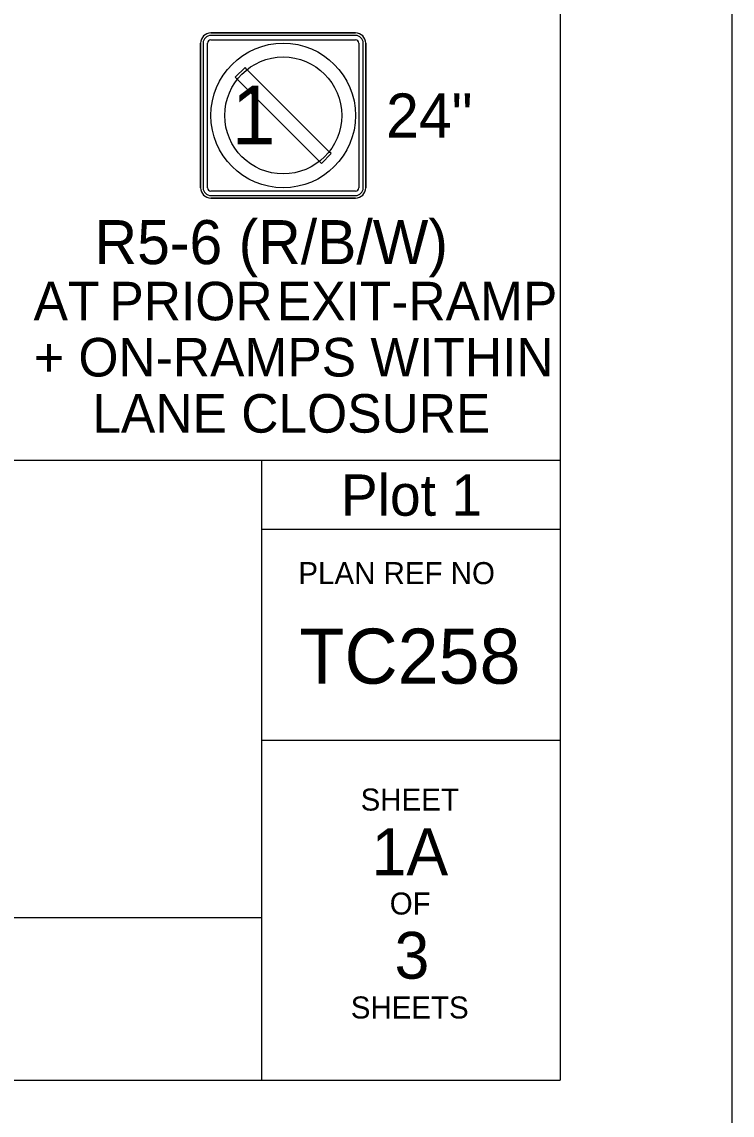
# Model space of a CAD drawing. Extents: x 99999 to 100116, y 99995 to 100013.
# Drawn here: x 100014.772 to 100016.062, y 99999.937 to 100001.922 of the extents above; entities that cross this region are included whole.
import ezdxf

# ---------------------------------------------------------------- set-up
doc = ezdxf.new("R2010")
doc.units = 0
for name, color, linetype in [('SH_GI_PlotLimits', 7, 'Continuous'), ('SH_GI_SheetBorder', 7, 'Continuous'), ('SH_GI_SheetLocationText', 7, 'Continuous'), ('SH_GI_SheetTextInCells', 7, 'Continuous'), ('SH_GI_TitleBlockText', 7, 'Continuous'), ('TR_SN_ConstructionSigns', 7, 'Continuous')]:
    doc.layers.add(name, color=color, linetype=linetype)

msp = doc.modelspace()

# ---------------------------------------------------------------- linework, layer by layer
at = {"layer": 'SH_GI_PlotLimits'}
msp.add_lwpolyline([(99999.0625, 99999.6875), (100016.0625, 99999.6875), (100016.0625, 100010.6875), (99999.0625, 100010.6875)], close=True, dxfattribs=at)
at = {"layer": 'SH_GI_SheetBorder'}
for p, q in [((100015.75, 100010.375), (100015.75, 100000)), ((100000, 100001.1259), (100015.75, 100001.1259)), ((100015.2079, 100001.1259), (100015.2079, 100000)), ((100015.2079, 100001.0008), (100015.75, 100001.0008)), ((100015.2079, 100000.6176), (100015.75, 100000.6176)), ((100012.2055, 100000.2955), (100015.2079, 100000.2955)), ((100000, 100000), (100015.75, 100000))]:
    msp.add_line(p, q, dxfattribs=at)
at = {"layer": 'TR_SN_ConstructionSigns'}
for p, q in [((100015.3783, 100001.9019), (100015.1158, 100001.9019)), ((100015.1158, 100001.9019), (100015.3783, 100001.9019)), ((100015.3783, 100001.9019), (100015.1158, 100001.9019)), ((100015.3783, 100001.8972), (100015.1158, 100001.8972)), ((100015.1158, 100001.8894), (100015.3783, 100001.8894)), ((100015.0971, 100001.8831), (100015.0971, 100001.6206)), ((100015.0971, 100001.6206), (100015.0971, 100001.8831)), ((100015.0971, 100001.8831), (100015.0971, 100001.6206)), ((100015.1018, 100001.8831), (100015.1018, 100001.6206)), ((100015.1096, 100001.6206), (100015.1096, 100001.8831)), ((100015.3846, 100001.8831), (100015.3846, 100001.6206)), ((100015.3924, 100001.6206), (100015.3924, 100001.8831)), ((100015.3971, 100001.6206), (100015.3971, 100001.8831)), ((100015.3971, 100001.8831), (100015.3971, 100001.6206)), ((100015.3971, 100001.6206), (100015.3971, 100001.8831)), ((100015.3783, 100001.6144), (100015.1158, 100001.6144)), ((100015.1158, 100001.6066), (100015.3783, 100001.6066)), ((100015.1158, 100001.6019), (100015.3783, 100001.6019)), ((100015.3783, 100001.6019), (100015.1158, 100001.6019)), ((100015.1158, 100001.6019), (100015.3783, 100001.6019))]:
    msp.add_line(p, q, dxfattribs=at)
msp.add_lwpolyline([(100015.3305, 100001.6861), (100015.1813, 100001.8353), (100015.1778, 100001.8389), (100015.1601, 100001.8212), (100015.3128, 100001.6685), (100015.3164, 100001.6649), (100015.3341, 100001.6826), (100015.3305, 100001.6861)], dxfattribs=at)
for radius in [0.1313, 0.1062]:
    msp.add_circle((100015.2471, 100001.7519), radius, dxfattribs=at)
for centre, radius, start, end in [((100015.1158, 100001.8831), 0.0187, 90, 180), ((100015.1158, 100001.8831), 0.0187, 90, 180), ((100015.1158, 100001.8831), 0.0187, 90, 180), ((100015.1158, 100001.8831), 0.0141, 90, 180), ((100015.1158, 100001.8831), 0.00625, 90, 180), ((100015.3783, 100001.8831), 0.0187, 0, 90), ((100015.3783, 100001.8831), 0.0187, 0, 90), ((100015.3783, 100001.8831), 0.0187, 0, 90), ((100015.3783, 100001.8831), 0.0141, 0, 90), ((100015.3783, 100001.8831), 0.00625, 0, 90), ((100015.1158, 100001.6206), 0.0187, 180, 270), ((100015.1158, 100001.6206), 0.0187, 180, 270), ((100015.1158, 100001.6206), 0.0187, 180, 270), ((100015.1158, 100001.6206), 0.0141, 180, 270), ((100015.1158, 100001.6206), 0.00625, 180, 270), ((100015.3783, 100001.6206), 0.0141, 270, 0), ((100015.3783, 100001.6206), 0.00625, 270, 0), ((100015.3783, 100001.6206), 0.0187, 270, 0), ((100015.3783, 100001.6206), 0.0187, 270, 0), ((100015.3783, 100001.6206), 0.0187, 270, 0)]:
    msp.add_arc(centre, radius, start, end, dxfattribs=at)

# ---------------------------------------------------------------- texts
at = {"layer": 'SH_GI_SheetBorder'}
msp.add_text('PLAN REF NO', height=0.040032, dxfattribs=at).set_placement((100015.2747, 100000.9008))
at = {"layer": 'SH_GI_SheetLocationText'}
msp.add_text('Plot 1', height=0.075, dxfattribs=at).set_placement((100015.3518, 100001.025))
at = {"layer": 'SH_GI_SheetTextInCells'}
for s, p in [('SHEET', (100015.3877, 100000.4896)), ('OF', (100015.4406, 100000.3008)), ('SHEETS', (100015.3698, 100000.112))]:
    msp.add_text(s, height=0.04003, dxfattribs=at).set_placement(p)
at = {"layer": 'SH_GI_TitleBlockText'}
for s, height, p in [('TC258', 0.1, (100015.2767, 100000.72)), ('1A', 0.085, (100015.4076, 100000.3723)), ('3', 0.085, (100015.4493, 100000.1843))]:
    msp.add_text(s, height=height, dxfattribs=at).set_placement(p)
at = {"layer": 'TR_SN_ConstructionSigns'}
msp.add_text('1', height=0.1065, dxfattribs=at).set_placement((100015.1538, 100001.6994))
for s, height, p in [('24"', 0.08, (100015.434, 100001.7119)), ('R5-6 (R/B/W)', 0.08, (100014.9045, 100001.4819)), ('AT', 0.07, (100014.7937, 100001.3799)), ('PRIOR', 0.07, (100014.9314, 100001.3799)), ('EXIT-RAMP', 0.07, (100015.2353, 100001.3799)), ('+ ON-RAMPS WITHIN', 0.07, (100014.7944, 100001.2779)), ('LANE CLOSURE', 0.07, (100014.9003, 100001.1759))]:
    msp.add_text(s, height=height, rotation=360, dxfattribs=at).set_placement(p)

doc.saveas('drawing.dxf')
